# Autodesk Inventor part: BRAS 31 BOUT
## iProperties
Created: 2004-11
Part Number: BRAS 31 BOUT
Document SubType Name: Modeling
Designer: Bruno
Manufacturer: Standard
Standards Organization: Custom
Author: Bruno
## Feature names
1. Base1
